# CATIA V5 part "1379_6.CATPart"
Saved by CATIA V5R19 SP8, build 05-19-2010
Part number: 6
Bounding box of the stored display mesh (mm): x -5 to 2.381, y 21.619 to 49.888, z 6.5 to 36.921
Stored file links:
  C:\Users\ThinkMotion\Desktop\EU_thinkMotion\iao\IAO_MMS_Groupe3\bblot\bblot\1379_6.CATPart
  C:\Users\ThinkMotion\Desktop\EU_thinkMotion\iao\IAO_MMS_Groupe3\bblot\bblot\1379_Squelette.CATPart
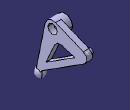
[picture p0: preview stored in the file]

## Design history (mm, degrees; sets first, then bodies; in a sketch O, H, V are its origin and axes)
Body1 (main body)
  Point1 to Point5: stored without definition
  Sketch1 on yz-plane, origin (0, 0, 0), H (0, 1, 0), V (0, 0, 1)
    point P1 (23.0142, 9.2031)
    line L1 (23.0142, 9.2031) -> (28.0823, 33.807)
    arc A1 centre (32, 33) radius 4 from (28.0823, 33.807) to (33.5024, 36.7071) cw
    point P3 (32, 33)
    line L2 (33.5024, 36.7071) -> (48.1268, 30.7804)
    arc A2 centre (47, 28) radius 3 from (48.1268, 30.7804) to (46.1198, 25.132) cw
    point P6 (47, 28)
    line L3 (46.1198, 25.132) -> (36.698, 28.0236)
    arc A3 centre (35.8178, 25.1556) radius 3 from (36.698, 28.0236) to (33.0909, 26.4063) ccw
    line L4 (33.0909, 26.4063) -> (24.9148, 8.5804)
    point P11 (24.9148, 8.5804)
    arc A4 centre (24, 9) radius 1.0065 from (24.9148, 8.5804) to (23.0142, 9.2031) cw
    point P12 (24, 9)
    reference projected point E1 (32, 33) from Point2
    reference projected point E2 (24, 9) from Point4
    reference projected point E3 (47, 28) from Point5
    circle A5 centre (32, 33) radius 2.5
    construction line L5 (47, 28) -> (32, 33)
    axis line L6 (32, 33) -> (32, 22.7061)
    radius A2 = 3
    distance P11 P1 = 2
    radius A3 = 3
    angle L2 L3 = 5
    radius A5 = 2.5
    radius A1 = 4
    angle L1 L4 = 13
    tangency: A1 L1, A2 L2, A3 L3, A4 L4, A1 L2, L4 A3, L1 A4, A2 L3
    coincidence: P3 E1, P12 E2, P6 E3
    vertical: L6 V
  Pad1: profile Sketch1, direction (1, 0, 0), length 1.5, opposite side length 1.5
  Point6: stored without definition
  Sketch2 on yz-plane, origin (0, 0, 0), H (0, 1, 0), V (0, 0, 1)
    arc A1 centre (24, 9) radius 2.5 from (24, 11.5) to (24, 6.5) ccw
    point P1 (24, 9)
    reference projected point E1 (24, 9) from Point6
    axis line L1 (24, 11.5) -> (24, 6.5)
    point P3 (24, 6.5)
    line L2 (24, 11.5) -> (24, 6.5)
    point P4 (24, 6.5)
    radius A1 = 2.5
    coincidence: P1 E1, L1 P1, P4 A1, L2 L1, P3 P4
    vertical: L1 V
  Shaft1: profile Sketch2, axis Sketch2.L1, angle 360
  Point7: stored without definition
  Sketch3 on start face of Pad1, origin (-1.5, 0, 0), H (0, 1, 0), V (0, 0, 1)
    circle A1 centre (47, 28) radius 1.5
    point P1 (47, 28)
    reference projected point E1 (47, 28) from Point10
    radius A1 = 1.5
    coincidence: P1 E1
  Pad2: profile Sketch3, direction (-1, 0, 0), length 2
  Sketch4 on start face of Pad1, origin (-1.5, 0, 0), H (0, -1, 0), V (0, 0, 1)
    circle A1 centre (-32, 33) radius 4
    reference projected arc E1 centre (-32, 33) radius 4 from (-28.0303, 33.4917) to (-33.6192, 36.6576) ccw from edge [start face of Pad1 | face of Pad1 from Sketch1.A1]
    circle A2 centre (-32, 33) radius 2.5
    reference projected circle E2 centre (-32, 33) radius 2.5 from edge [face of Pad1 from Sketch1.A5 | start face of Pad1]
    reference projected circle E3 centre (-32, 33) radius 2.5 from edge [face of Pad1 from Sketch1.A5 | start face of Pad1]
    coincidence: A1 E1, A2 E3
    concentricity: A2 E2
  Pad3: profile Sketch4, direction (-1, 0, 0), length 3.5
  Point8: type Center, Curve edge [face of Pad2 from Sketch3.A1 | start face of Pad1]
  Point9: type Center, Curve face of Shaft1 from Sketch2.A1
  Sketch5 on start face of Pad1, origin (-1.5, 0, 0), H (0, -1, 0), V (0, 0, 1)
    line L1 (-48.6099, 25.4685) -> (-26.0931, 11.1492)
    point P1 (-48.6099, 25.4685)
    point P2 (-26.0931, 11.1492)
    line L2 (-26.0931, 11.1492) -> (-28.3952, 16.1685)
    line L3 (-44.8391, 26.6258) -> (-48.6099, 25.4685)
    reference projected arc E1 centre (-47, 28) radius 3 from (-48.2144, 30.7432) to (-46.0293, 25.1614) ccw from edge [start face of Pad1 | face of Pad1 from Sketch1.A2]
    reference projected line E2 (-24.9199, 8.5915) -> (-32.5683, 25.2668) from edge [start face of Pad1 | face of Pad1 from Sketch1.L4]
    line L4 (-44.8391, 26.6258) -> (-28.3952, 16.1685)
    reference projected arc E3 centre (-47, 28) radius 3 from (-48.2144, 30.7432) to (-46.0293, 25.1614) ccw from edge [start face of Pad1 | face of Pad1 from Sketch1.A2]
    reference projected line E4 (-24.9199, 8.5915) -> (-32.5683, 25.2668) from edge [start face of Pad1 | face of Pad1 from Sketch1.L4]
    reference projected line E5 (-36.4462, 28.1008) -> (-46.0061, 25.1669) from edge [start face of Pad1 | face of Pad1 from Sketch1.L3]
    reference projected point E6 (-24, 9) from edge
    reference projected point E7 (-24, 9) from edge
    reference projected point E8 (-24, 9) from edge
    distance L4 L1 = 3
    distance E6 E7 = 0 (reference)
    distance P2 E8 = 3
    tangency: L1 E1
    coincidence: E2 P2, P1 E3, L2 E4
    parallelism: L3 E5
  Pad4: profile Sketch5, direction (-1, 0, 0), up to end face of Pad1
  Fillet1: radius 2, on edge [face of Pad4 from Sketch5.L1 | face of Pad1 from Sketch1.L4]
  Point10: stored without definition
